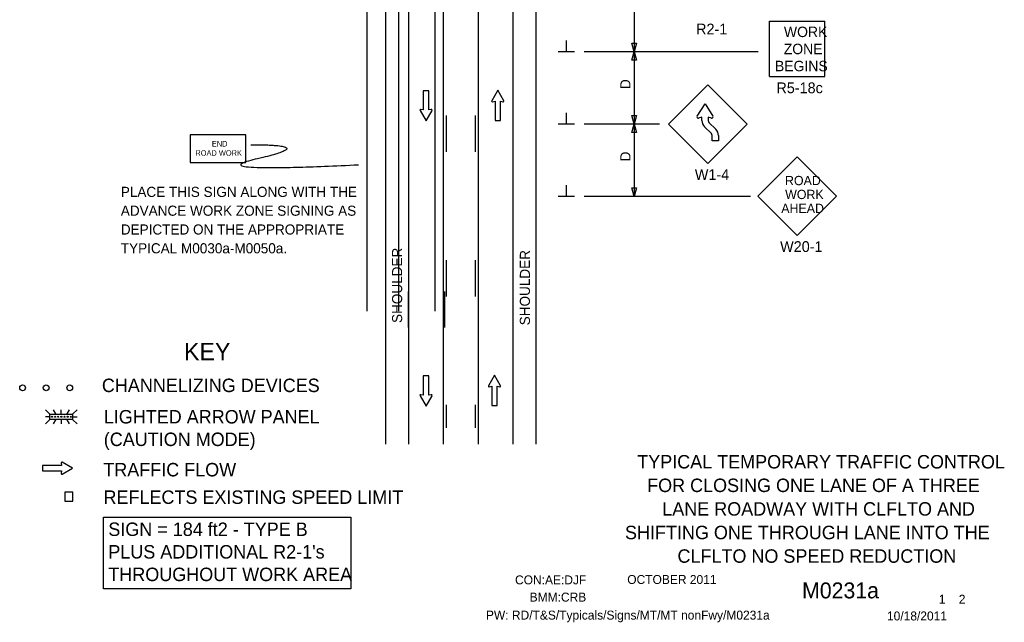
# Model space of a CAD drawing. Extents: x 16748 to 18296, y 7218 to 8262.
# Drawn here: x 16748 to 17429, y 7218 to 7635 of the extents above; entities that cross this region are included whole.
import ezdxf

# ---------------------------------------------------------------- set-up
doc = ezdxf.new("R2010")
doc.units = 0
for name, color, linetype in [('BORDER', 7, 'Continuous'), ('BORDER_SIGNAL_WO', 7, 'Continuous'), ('MT_SCRATCH_LEVEL_A', 7, 'Continuous'), ('MT_SCRATCH_LEVEL_E', 7, 'Continuous'), ('PAVT_EDGE_EX', 7, 'Continuous'), ('SCRATCH_LEVEL_C', 7, 'Continuous'), ('TRAFFIC_SIGNS_PR', 7, 'Continuous'), ('TYPICAL_EX', 7, 'Continuous'), ('TYPICAL_TEXT_DIMEN_EX', 7, 'Continuous'), ('TYPICAL_TEXT_DIMEN_PR', 7, 'Continuous')]:
    doc.layers.add(name, color=color, linetype=linetype)

msp = doc.modelspace()

# ---------------------------------------------------------------- linework, layer by layer
at = {"layer": 'BORDER'}
for p, q in [((17017.08, 8216.25), (17017.08, 7341.25)), ((17089.08, 7765.38), (17089.08, 7341.25))]:
    msp.add_line(p, q, dxfattribs=at)
at = {"layer": 'MT_SCRATCH_LEVEL_A'}
for p, q in [((17041.08, 8216.25), (17041.08, 7341.25)), ((17065.08, 7709.73), (17065.08, 7341.25))]:
    msp.add_line(p, q, dxfattribs=at)
for points in [[(17043.08, 7568.47), (17043.08, 7543.47)], [(17063.08, 7568.47), (17063.08, 7543.47)], [(17043.08, 7468.47), (17043.08, 7443.47)], [(17063.08, 7468.47), (17063.08, 7443.47)], [(17043.08, 7368.47), (17043.08, 7352.54)], [(17063.08, 7368.47), (17063.08, 7352.54)]]:
    msp.add_lwpolyline(points, dxfattribs=at)
at = {"layer": 'MT_SCRATCH_LEVEL_E'}
for p, q in [((17078.69, 7585.93), (17074.58, 7578.69)), ((17078.69, 7585.93), (17074.58, 7578.69)), ((17082.83, 7578.69), (17078.69, 7585.93)), ((17082.83, 7578.69), (17078.69, 7585.93)), ((17031.01, 7585.65), (17027.26, 7585.65)), ((17027.26, 7585.65), (17027.26, 7572.39)), ((17031.01, 7585.65), (17027.26, 7585.65)), ((17027.26, 7585.65), (17027.26, 7572.39)), ((17031.01, 7572.39), (17031.01, 7585.65)), ((17031.01, 7572.39), (17031.01, 7585.65)), ((17027.26, 7572.39), (17025.49, 7572.7)), ((17027.26, 7572.39), (17025.49, 7572.7)), ((17032.78, 7572.7), (17031.01, 7572.39)), ((17032.78, 7572.7), (17031.01, 7572.39)), ((17075.06, 7578.01), (17076.84, 7578.32)), ((17075.06, 7578.01), (17076.84, 7578.32)), ((17076.84, 7578.32), (17076.84, 7565.07)), ((17076.84, 7578.32), (17076.84, 7565.07)), ((17080.58, 7565.07), (17080.58, 7578.32)), ((17080.58, 7578.32), (17082.36, 7578.01)), ((17080.58, 7565.07), (17080.58, 7578.32)), ((17080.58, 7578.32), (17082.36, 7578.01)), ((17025.01, 7572.02), (17029.15, 7564.78)), ((17025.01, 7572.02), (17029.15, 7564.78)), ((17029.15, 7564.78), (17033.27, 7572.02)), ((17029.15, 7564.78), (17033.27, 7572.02)), ((17076.84, 7565.07), (17080.58, 7565.07)), ((17076.84, 7565.07), (17080.58, 7565.07)), ((17031.01, 7388.42), (17027.26, 7388.42)), ((17027.26, 7388.42), (17027.26, 7375.16)), ((17031.01, 7388.42), (17027.26, 7388.42)), ((17027.26, 7388.42), (17027.26, 7375.16)), ((17031.01, 7375.16), (17031.01, 7388.42)), ((17031.01, 7375.16), (17031.01, 7388.42)), ((17076.52, 7388.88), (17072.41, 7381.64)), ((17076.52, 7388.88), (17072.41, 7381.64)), ((17080.67, 7381.64), (17076.52, 7388.88)), ((17080.67, 7381.64), (17076.52, 7388.88)), ((17025.01, 7374.79), (17029.15, 7367.55)), ((17025.01, 7374.79), (17029.15, 7367.55)), ((17027.26, 7375.16), (17025.49, 7375.48)), ((17027.26, 7375.16), (17025.49, 7375.48)), ((17029.15, 7367.55), (17033.27, 7374.79)), ((17029.15, 7367.55), (17033.27, 7374.79)), ((17032.78, 7375.48), (17031.01, 7375.16)), ((17032.78, 7375.48), (17031.01, 7375.16)), ((17072.89, 7380.95), (17074.67, 7381.27)), ((17072.89, 7380.95), (17074.67, 7381.27)), ((17074.67, 7381.27), (17074.67, 7368.01)), ((17074.67, 7381.27), (17074.67, 7368.01)), ((17078.41, 7368.01), (17078.41, 7381.27)), ((17078.41, 7381.27), (17080.19, 7380.95)), ((17078.41, 7368.01), (17078.41, 7381.27)), ((17078.41, 7381.27), (17080.19, 7380.95)), ((17074.67, 7368.01), (17078.41, 7368.01)), ((17074.67, 7368.01), (17078.41, 7368.01)), ((16776.79, 7328.25), (16777.11, 7326.47)), ((16776.79, 7328.25), (16777.11, 7326.47)), ((16784.72, 7324.62), (16777.48, 7328.73)), ((16784.72, 7324.62), (16777.48, 7328.73)), ((16777.11, 7326.47), (16763.85, 7326.47)), ((16763.85, 7326.47), (16763.85, 7322.73)), ((16777.11, 7326.47), (16763.85, 7326.47)), ((16763.85, 7326.47), (16763.85, 7322.73)), ((16763.85, 7322.73), (16777.11, 7322.73)), ((16763.85, 7322.73), (16777.11, 7322.73)), ((16777.11, 7322.73), (16776.79, 7320.95)), ((16777.11, 7322.73), (16776.79, 7320.95)), ((16777.48, 7320.47), (16784.72, 7324.62)), ((16777.48, 7320.47), (16784.72, 7324.62))]:
    msp.add_line(p, q, dxfattribs=at)
for centre, start, end in [((17025.42, 7572.24), 80.03619, 209.77312), ((17025.42, 7572.24), 80.03619, 209.77312), ((17032.86, 7572.24), 330.42484, 99.96381), ((17032.86, 7572.24), 330.42484, 99.96381), ((17074.99, 7578.47), 150.42484, 279.96381), ((17074.99, 7578.47), 150.42484, 279.96381), ((17082.43, 7578.47), 260.03619, 29.77312), ((17082.43, 7578.47), 260.03619, 29.77312), ((17072.81, 7381.41), 150.42484, 279.96381), ((17072.81, 7381.41), 150.42484, 279.96381), ((17080.26, 7381.42), 260.03619, 29.77312), ((17080.26, 7381.42), 260.03619, 29.77312), ((17025.42, 7375.02), 80.03619, 209.77312), ((17025.42, 7375.02), 80.03619, 209.77312), ((17032.86, 7375.02), 330.42484, 99.96381), ((17032.86, 7375.02), 330.42484, 99.96381), ((16777.25, 7328.32), 60.42484, 189.96381), ((16777.25, 7328.32), 60.42484, 189.96381), ((16777.25, 7320.88), 170.03619, 299.77312), ((16777.25, 7320.88), 170.03619, 299.77312)]:
    msp.add_arc(centre, 0.463, start, end, dxfattribs=at)
at = {"layer": 'PAVT_EDGE_EX'}
for p, q in [((16988.15, 8262.34), (16988.15, 7433.15)), ((17010.15, 8262.34), (17010.15, 7433.15)), ((17035.15, 8262.34), (17035.15, 7433.15)), ((17001.08, 8216.25), (17001.08, 7341.25)), ((17105.08, 8216.25), (17105.08, 7341.25))]:
    msp.add_line(p, q, dxfattribs=at)
for points in [[(17017.08, 7421.93), (17017.08, 7446.93)], [(17042.08, 7421.93), (17042.08, 7446.93)]]:
    msp.add_lwpolyline(points, dxfattribs=at)
at = {"layer": 'SCRATCH_LEVEL_C'}
msp.add_lwpolyline([(16806.07, 7290.9), (16977.08, 7290.9), (16977.08, 7241.22), (16806.07, 7241.22)], close=True, dxfattribs=at)
at = {"layer": 'TRAFFIC_SIGNS_PR'}
for p, q in [((17266.66, 7595.38), (17266.66, 7633.78)), ((17266.66, 7633.78), (17305.06, 7633.78)), ((17305.06, 7595.38), (17305.06, 7633.78)), ((17266.66, 7595.38), (17305.06, 7595.38)), ((17196.89, 7562.54), (17224.04, 7589.7)), ((17251.2, 7562.54), (17224.04, 7589.7)), ((17224.04, 7535.39), (17196.89, 7562.54)), ((17226.46, 7556.02), (17221.75, 7560.74)), ((17226.46, 7556.02), (17221.75, 7560.74)), ((17251.2, 7562.54), (17224.04, 7535.39)), ((17229.51, 7559.08), (17224.8, 7563.79)), ((17224.8, 7563.79), (17229.51, 7559.08)), ((17285.86, 7539.99), (17258.67, 7512.8)), ((17313.05, 7512.8), (17285.86, 7539.99)), ((17258.67, 7512.8), (17285.86, 7485.62)), ((17285.86, 7485.62), (17313.05, 7512.8)), ((16765.96, 7365.07), (16768.78, 7362.25)), ((16773.05, 7362.25), (16771.42, 7365.07)), ((16776.86, 7362.25), (16776.86, 7365.07)), ((16781, 7362.25), (16782.62, 7365.07)), ((16784.95, 7362.25), (16787.77, 7365.07)), ((16768.78, 7360.22), (16765.96, 7360.22)), ((16765.96, 7355.37), (16768.78, 7358.18)), ((16770.41, 7360.22), (16770.41, 7360.22)), ((16771.39, 7355.36), (16773.02, 7358.18)), ((16772.59, 7360.22), (16772.59, 7360.22)), ((16774.76, 7360.22), (16774.76, 7360.22)), ((16776.86, 7358.18), (16776.86, 7355.36)), ((16776.94, 7360.22), (16776.94, 7360.22)), ((16779.11, 7360.22), (16779.11, 7360.22)), ((16782.65, 7355.36), (16781.02, 7358.18)), ((16781.28, 7360.22), (16781.28, 7360.22)), ((16783.46, 7360.22), (16783.46, 7360.22)), ((16784.95, 7360.22), (16787.77, 7360.22)), ((16784.95, 7358.18), (16787.77, 7355.36))]:
    msp.add_line(p, q, dxfattribs=at)
for points in [[(17216.59, 7568.07), (17222.08, 7576.68), (17227.56, 7568.07)], [(17216.59, 7568.07), (17222.08, 7576.68), (17227.56, 7568.07)], [(17219.92, 7565.05), (17219.92, 7567.42), (17217.55, 7566.77)], [(17219.92, 7565.05), (17219.92, 7567.42), (17217.55, 7566.77)], [(17226.6, 7566.77), (17224.24, 7567.42), (17224.24, 7565.12)], [(17226.6, 7566.77), (17225.76, 7567), (17224.24, 7567.42), (17224.24, 7565.12)], [(17231.38, 7554.66), (17231.38, 7550.96), (17227.06, 7550.96), (17227.06, 7554.66)]]:
    msp.add_lwpolyline(points, dxfattribs=at)
for points in [[(16866.03, 7535.94), (16904.43, 7535.94), (16904.43, 7555.14), (16866.03, 7555.14)], [(16784.72, 7358.42), (16769.01, 7358.42), (16769.01, 7362.02), (16784.72, 7362.02)], [(16779.26, 7301.81), (16784.85, 7301.81), (16784.85, 7307.98), (16779.26, 7307.98)]]:
    msp.add_lwpolyline(points, close=True, dxfattribs=at)
for centre, radius in [((16750.12, 7380.22), 2), ((16766.42, 7380.22), 2), ((16782.72, 7380.22), 2), ((16770.43, 7360.22), 0.379), ((16772.59, 7360.22), 0.379), ((16774.76, 7360.22), 0.379), ((16776.94, 7360.22), 0.379), ((16779.11, 7360.22), 0.379), ((16781.28, 7360.22), 0.379), ((16783.46, 7360.22), 0.379)]:
    msp.add_circle(centre, radius, dxfattribs=at)
for centre, radius, start, end in [((17217.33, 7567.6), 0.866, 147.7292, 285.31719), ((17217.33, 7567.6), 0.866, 147.71964, 285.32011), ((17207.48, 7573.86), 10.8, 327.53351, 327.54311), ((17220.41, 7556.35), 10.8, 105.31922, 105.32004), ((17226.83, 7567.6), 0.866, 254.61481, 32.47119), ((17226.09, 7565.12), 6.17, 180.61811, 225.78746), ((17226.09, 7565.12), 6.17, 180.62445, 225.23128), ((17226.09, 7565.12), 1.85, 180, 225.78746), ((17226.09, 7565.12), 1.85, 179.8762, 225.7877), ((17225.21, 7554.66), 6.17, 0, 45.78828), ((17225.21, 7554.66), 1.85, 0, 47.62801)]:
    msp.add_arc(centre, radius, start, end, dxfattribs=at)
msp.add_open_spline([(16908.03, 7548.33), (16955.26, 7548.33), (16870.24, 7528.98), (16982.54, 7534.47)], degree=2, dxfattribs=at)
at = {"layer": 'TYPICAL_EX'}
for p, q in [((17126.21, 7612.61), (17126.21, 7620.39)), ((17131.83, 7612.61), (17120.58, 7612.61)), ((17126.21, 7562.61), (17126.21, 7570.39)), ((17131.83, 7562.61), (17120.58, 7562.61)), ((17126.21, 7512.61), (17126.21, 7520.39)), ((17131.83, 7512.61), (17120.58, 7512.61))]:
    msp.add_line(p, q, dxfattribs=at)
at = {"layer": 'TYPICAL_TEXT_DIMEN_PR'}
for p, q in [((17173.08, 7662.61), (17173.08, 7612.61)), ((17173.08, 7612.61), (17171.51, 7618.47)), ((17171.51, 7618.47), (17173.08, 7618.47)), ((17173.08, 7618.47), (17174.65, 7618.47)), ((17174.65, 7618.47), (17173.08, 7612.61)), ((17258.94, 7612.61), (17138.39, 7612.61)), ((17171.51, 7606.74), (17173.08, 7612.61)), ((17173.08, 7606.74), (17171.51, 7606.74)), ((17173.08, 7612.61), (17174.65, 7606.74)), ((17173.08, 7612.61), (17173.08, 7562.61)), ((17174.65, 7606.74), (17173.08, 7606.74)), ((17173.08, 7562.61), (17171.51, 7568.47)), ((17171.51, 7568.47), (17173.08, 7568.47)), ((17173.08, 7568.47), (17174.65, 7568.47)), ((17174.65, 7568.47), (17173.08, 7562.61)), ((17190.67, 7562.61), (17138.39, 7562.61)), ((17171.51, 7556.74), (17173.08, 7562.61)), ((17173.08, 7562.61), (17174.65, 7556.74)), ((17173.08, 7562.61), (17173.08, 7512.61)), ((17173.08, 7556.74), (17171.51, 7556.74)), ((17174.65, 7556.74), (17173.08, 7556.74)), ((17173.08, 7512.61), (17171.51, 7518.47)), ((17171.51, 7518.47), (17173.08, 7518.47)), ((17173.08, 7518.47), (17174.65, 7518.47)), ((17174.65, 7518.47), (17173.08, 7512.61)), ((17253.56, 7512.61), (17138.39, 7512.61))]:
    msp.add_line(p, q, dxfattribs=at)

# ---------------------------------------------------------------- texts
at = {"layer": 'BORDER_SIGNAL_WO'}
for s, height, p in [('TYPICAL TEMPORARY TRAFFIC CONTROL', 9.3, (17175.21, 7324.45)), ('FOR CLOSING ONE LANE OF A THREE', 9.3, (17182.06, 7308.15)), ('LANE ROADWAY WITH CLFLTO AND', 9.3, (17192.52, 7291.85)), ('SHIFTING ONE THROUGH LANE INTO THE ', 9.3, (17166.75, 7275.55)), ('CLFLTO NO SPEED REDUCTION', 9.3, (17203.04, 7259.25)), ('CON:AE:DJF  ', 6.2, (17090.69, 7244.31)), ('    OCTOBER 2011    ', 6.2, (17159.08, 7244.59)), ('    M0231a   ', 11, (17272.86, 7234.63)), ('BMM:CRB   ', 6.2, (17100.81, 7232.42)), (' 1    2 ', 6.2, (17381.45, 7230.95)), ('PW: RD/T&S/Typicals/Signs/MT/MT nonFwy/M0231a  ', 6.2, (17070.55, 7219.96)), ('10/18/2011    ', 6.2, (17347.93, 7219.38))]:
    msp.add_text(s, height=height, dxfattribs=at).set_placement(p)
at = {"layer": 'SCRATCH_LEVEL_C'}
for s, p in [('SIGN = 184 ft2 - TYPE B', (16809.41, 7277.78)), ("PLUS ADDITIONAL R2-1's", (16809.41, 7262.18)), ('THROUGHOUT WORK AREA', (16809.41, 7246.58))]:
    msp.add_text(s, height=9.3, dxfattribs=at).set_placement(p)
at = {"layer": 'TRAFFIC_SIGNS_PR'}
for s, height, p in [('R2-1', 7.44, (17215.91, 7624.59)), ('WORK', 7.217, (17276.66, 7622.74)), ('ZONE', 7.217, (17276.54, 7610.93)), ('BEGINS', 7.217, (17270.47, 7599.12)), ('R5-18c', 7.44, (17271.47, 7583.94)), ('END', 3.831, (16881.03, 7547.07)), ('ROAD WORK', 3.831, (16869.64, 7540.69)), ('W1-4', 7.44, (17215.04, 7523.95)), ('ROAD', 6.408, (17277.39, 7520.35)), ('PLACE THIS SIGN ALONG WITH THE', 7, (16818.06, 7512.2)), ('WORK', 6.408, (17277.5, 7510.74)), ('ADVANCE WORK ZONE SIGNING AS', 7, (16818.06, 7499.2)), ('AHEAD', 6.408, (17274.81, 7501.12)), ('DEPICTED ON THE APPROPRIATE', 7, (16818.06, 7486.2)), ('TYPICAL M0030a-M0050a.', 7, (16818.06, 7473.2)), ('W20-1', 7.449, (17274.02, 7474.16))]:
    msp.add_text(s, height=height, dxfattribs=at).set_placement(p)
at = {"layer": 'TYPICAL_TEXT_DIMEN_EX'}
for p in [(17012.63, 7425.07), (17101, 7423.46)]:
    msp.add_text('SHOULDER', height=7, rotation=90, dxfattribs=at).set_placement(p)
for s, height, p in [('KEY', 12, (16861.75, 7399.32)), ('CHANNELIZING DEVICES', 9.3, (16804.96, 7377.27)), ('LIGHTED ARROW PANEL', 9.3, (16806.28, 7355.57)), ('(CAUTION MODE)', 9.3, (16806.28, 7339.97)), ('TRAFFIC FLOW', 9.3, (16805.93, 7318.98)), ('REFLECTS EXISTING SPEED LIMIT', 9.3, (16806.07, 7299.97))]:
    msp.add_text(s, height=height, dxfattribs=at).set_placement(p)
at = {"layer": 'TYPICAL_TEXT_DIMEN_PR'}
for p in [(17170.52, 7586.82), (17170.52, 7536.82)]:
    msp.add_text('D', height=7, rotation=90, dxfattribs=at).set_placement(p)

doc.saveas('drawing.dxf')
